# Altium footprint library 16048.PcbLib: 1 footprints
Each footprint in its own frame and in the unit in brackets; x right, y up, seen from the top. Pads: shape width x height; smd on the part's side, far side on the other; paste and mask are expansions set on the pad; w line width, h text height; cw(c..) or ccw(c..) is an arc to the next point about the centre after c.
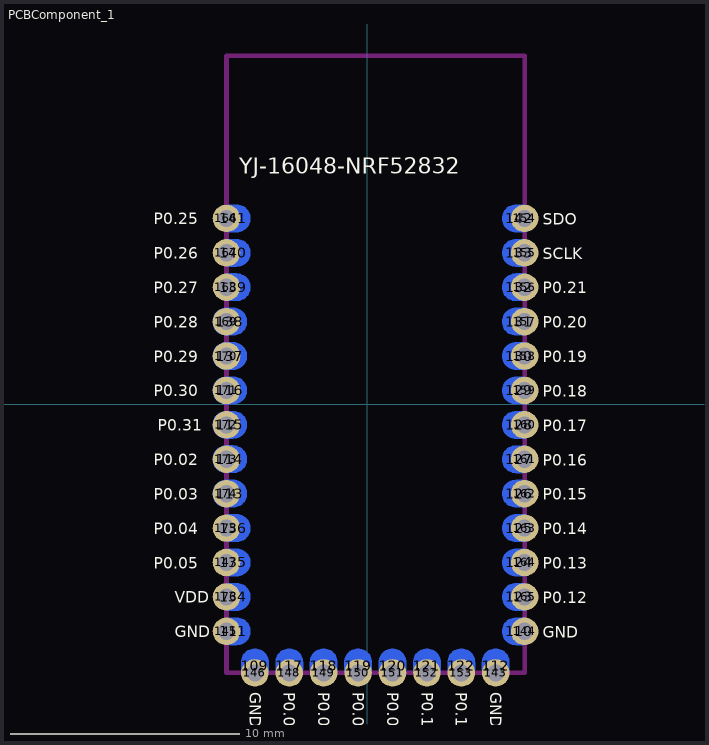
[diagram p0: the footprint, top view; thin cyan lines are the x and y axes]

## PCBComponent_1 [mm]
pads (68):
  oval 1.2x1.5 smd far side: 109(-4.894,-11.4) 112(5.606,-11.4) 117(-3.394,-11.4) 118(-1.894,-11.4) 119(-0.394,-11.4) 120(1.106,-11.4) 121(2.606,-11.4) 122(4.106,-11.4)
  oval 1.5x1.2 smd far side: 110(6.633,-9.897) 111(-5.834,-9.897) 113(-5.988,-3.896) 114(-5.988,-2.396) 115(-5.988,-0.896) 116(-5.988,0.604) 123(6.633,-8.397) 124(6.633,-6.897) 125(6.633,-5.397) 126(6.633,-3.897) 127(6.633,-2.397) 128(6.633,-0.897) 129(6.633,0.603) 130(6.633,2.103) 131(6.633,3.603) 132(6.633,5.103) 133(6.633,6.603) 134(-5.834,-8.397) 135(-5.834,-6.897) 136(-5.834,-5.397) 137(-5.988,2.104) 138(-5.988,3.603) 139(-5.834,5.103) 140(-5.834,6.603) 141(-5.834,8.103) 142(6.633,8.103)
  round 1.2 hole 0.75: 143(5.606,-11.712) 144(6.866,-9.897) 145(-6.13,-9.897) 146(-4.893,-11.712) 147(-6.13,-6.897) 148(-3.394,-11.712) 149(-1.894,-11.712) 150(-0.394,-11.712) 151(1.106,-11.712) 152(2.606,-11.712) 153(4.106,-11.712) 154(6.866,8.103) 155(6.866,6.603) 156(6.866,5.103) 157(6.866,3.603) 158(6.866,2.103) 159(6.866,0.603) 160(6.866,-0.897) 161(6.866,-2.397) 162(6.866,-3.897) 163(6.866,-5.397) 164(6.866,-6.897) 165(6.866,-8.397) 166(-6.13,8.103) 167(-6.13,6.603) 168(-6.13,5.103) 169(-6.13,3.603) 170(-6.13,2.103) 171(-6.13,0.603) 172(-6.13,-0.897) 173(-6.13,-2.397) 174(-6.13,-3.897) 175(-6.13,-5.397) 176(-6.13,-8.397)
Top Overlay:
  text "YJ-16048-NRF52832" at -5.567,10.049 h0.7
  text "SDO" at 7.653,7.829 h0.5
  text "SCLK" at 7.653,6.329 h0.5
  text "P0.21" at 7.653,4.829 h0.5
  text "P0.20" at 7.653,3.329 h0.5
  text "P0.19" at 7.653,1.829 h0.5
  text "P0.18" at 7.653,0.329 h0.5
  text "P0.17" at 7.653,-1.171 h0.5
  text "P0.16" at 7.653,-2.671 h0.5
  text "P0.15" at 7.653,-4.171 h0.5
  text "P0.14" at 7.653,-5.671 h0.5
  text "P0.13" at 7.653,-7.171 h0.5
  text "P0.12" at 7.653,-8.671 h0.5
  text "P0.25" at -9.297,7.839 h0.5
  text "P0.26" at -9.297,6.339 h0.5
  text "P0.27" at -9.297,4.839 h0.5
  text "P0.28" at -9.297,3.339 h0.5
  text "P0.29" at -9.297,1.839 h0.5
  text "P0.30" at -9.297,0.339 h0.5
  text "P0.31" at -9.13,-1.161 h0.5
  text "P0.02" at -9.297,-2.661 h0.5
  text "P0.03" at -9.297,-4.161 h0.5
  text "P0.04" at -9.297,-5.661 h0.5
  text "P0.05" at -9.297,-7.161 h0.5
  text "GND" at 7.653,-10.171 h0.5
  text "VDD" at -8.381,-8.661 h0.5
  text "GND" at -8.381,-10.161 h0.5
  text "GND" at -5.127,-12.551 h0.5
  text "P0.06" at -3.627,-12.551 h0.5
  text "P0.07" at -2.127,-12.551 h0.5
  text "P0.08" at -0.627,-12.551 h0.5
  text "P0.09" at 0.873,-12.551 h0.5
  text "P0.10" at 2.373,-12.551 h0.5
  text "P0.11" at 3.873,-12.551 h0.5
  text "GND" at 5.373,-12.551 h0.5
Bottom Overlay:
  text "P0.25" at -2.627,8.089 h0.5
  text "P0.26" at -2.647,6.559 h0.5
  text "P0.27" at -2.617,4.959 h0.5
  text "P0.28" at -2.727,3.479 h0.5
  text "P0.29" at -2.697,1.969 h0.5
  text "P0.30" at -2.757,0.829 h0.5
  text "P0.31" at -2.867,-1.051 h0.5
  text "P0.02" at -2.817,-2.421 h0.5
  text "P0.03" at -2.817,-4.041 h0.5
  text "P0.04" at -2.757,-5.841 h0.5
  text "P0.05" at -2.587,-7.011 h0.5
  text "VDD" at -3.527,-8.521 h0.5
  text "GND" at -4.997,-10.591 h0.5
  text "P0.06" at -3.387,-10.151 h0.5
  text "P0.07" at -2.087,-10.061 h0.5
  text "P0.08" at -0.577,-10.221 h0.5
  text "P0.09" at 0.903,-10.241 h0.5
  text "P0.10" at 2.243,-10.291 h0.5
  text "P0.11" at 3.373,-10.201 h0.5
  text "GND" at 5.793,-9.491 h0.5
  text "P0.12" at 5.623,-8.011 h0.5
  text "P0.13" at 5.653,-6.551 h0.5
  text "P0.14" at 5.623,-5.331 h0.5
  text "P0.15" at 5.623,-4.211 h0.5
  text "P0.16" at 5.623,-2.641 h0.5
  text "P0.17" at 5.623,-1.061 h0.5
  text "P0.18" at 5.653,0.369 h0.5
  text "P0.19" at 5.633,1.889 h0.5
  text "P0.20" at 5.583,3.469 h0.5
  text "P0.21" at 5.563,4.929 h0.5
  text "SCLK" at 5.593,6.639 h0.5
  text "SDO" at 5.463,7.869 h0.5
Keep-Out Layer:
  lines w0.2: -6.134,-11.712 -6.134,-10.527 ; -6.134,-11.702 -6.134,-10.517 ; -6.13,-11.712 -6.13,15.19 6.866,15.19 6.866,-11.712 -6.13,-11.712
